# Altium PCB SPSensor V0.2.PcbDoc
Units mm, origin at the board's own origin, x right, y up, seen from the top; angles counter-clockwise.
Board outline 20.98 x 57.97 mm, 4 copper layers (TopLayer, GND, PWR, BottomLayer); 80 components, 54 nets, 260 pads, 87 vias.
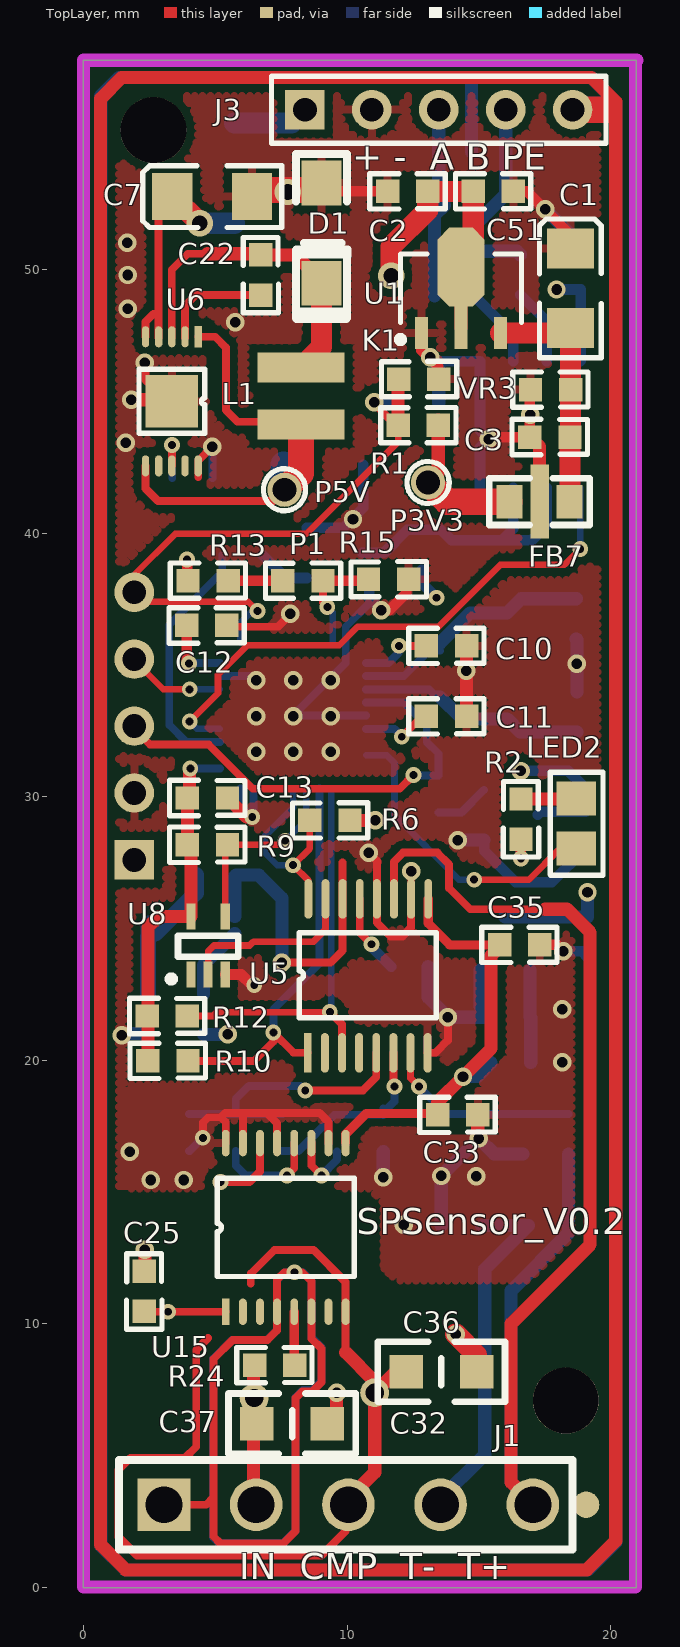
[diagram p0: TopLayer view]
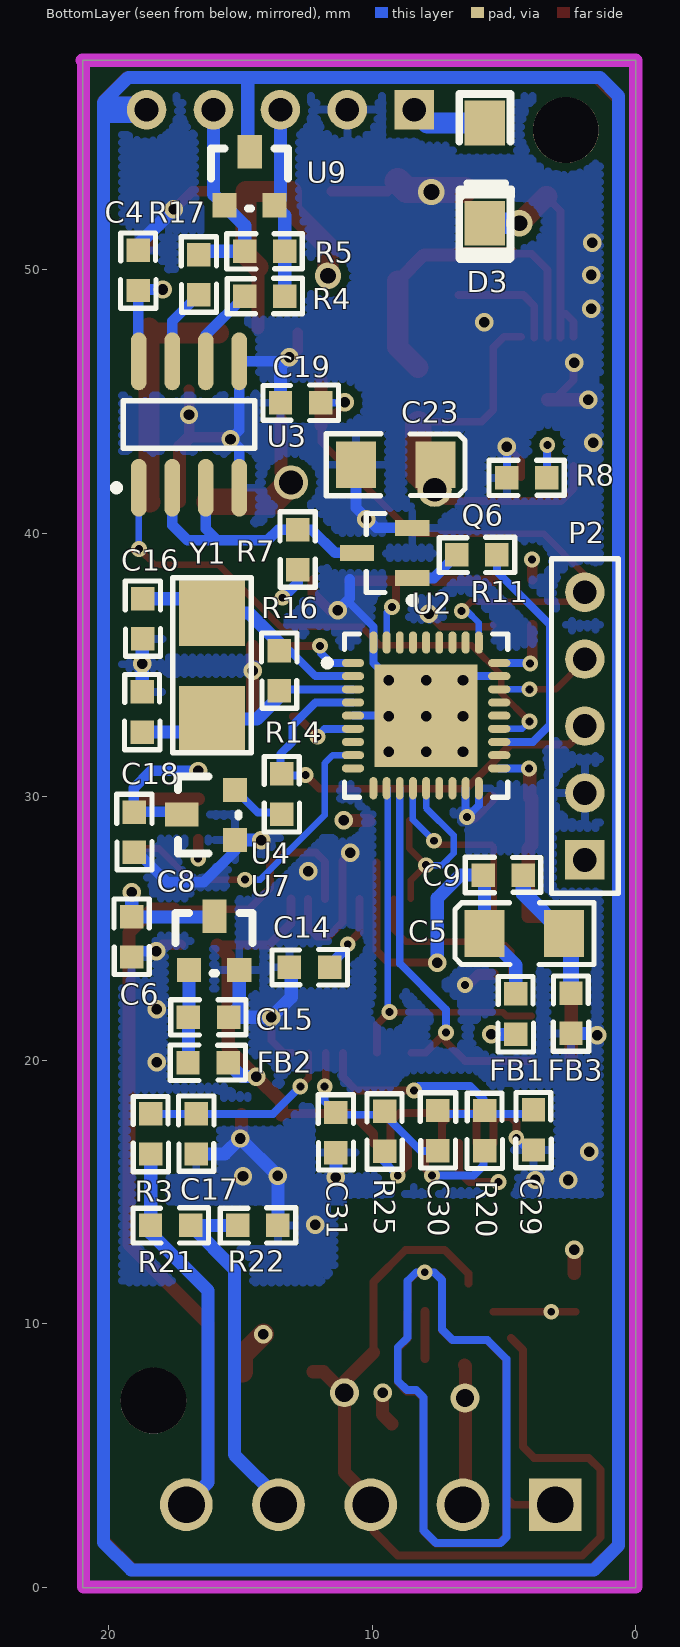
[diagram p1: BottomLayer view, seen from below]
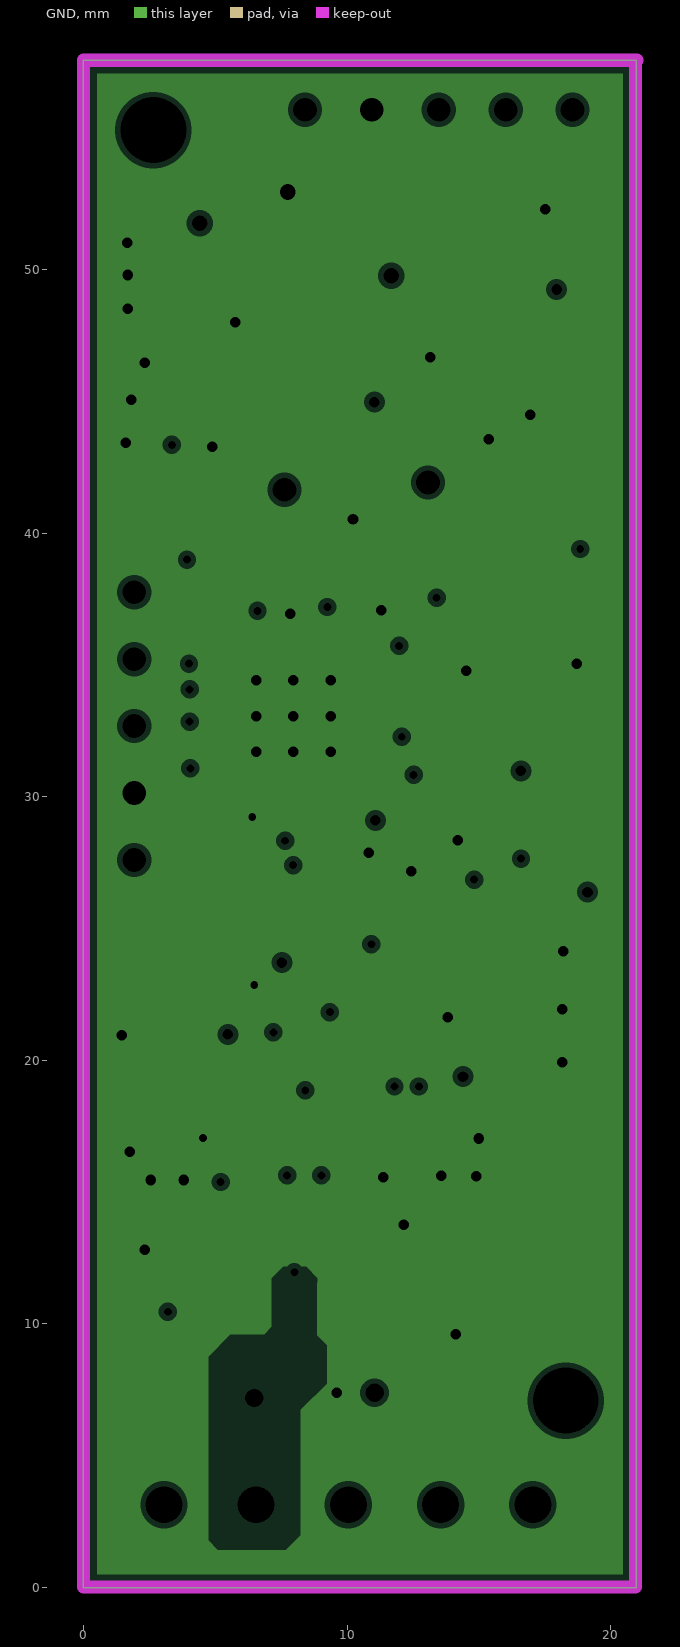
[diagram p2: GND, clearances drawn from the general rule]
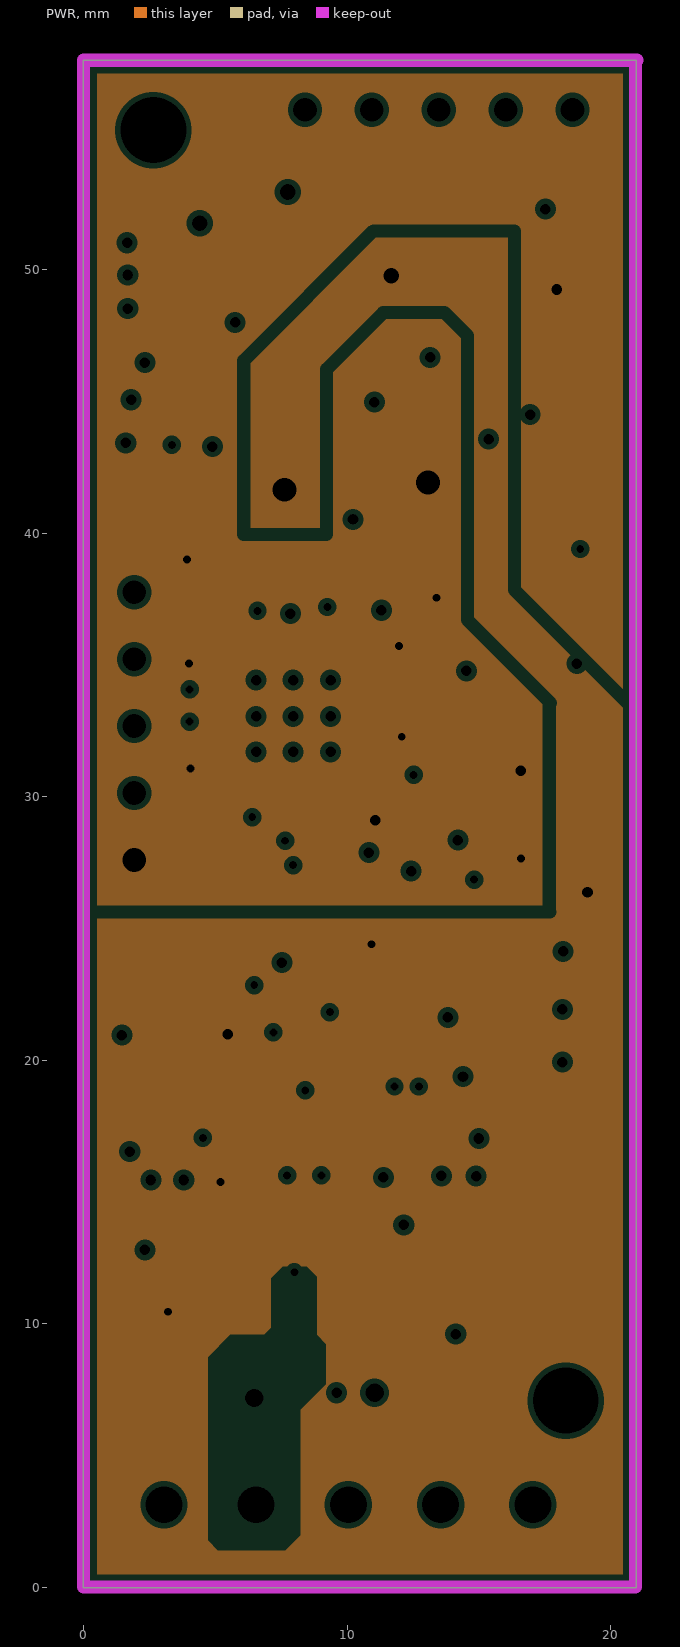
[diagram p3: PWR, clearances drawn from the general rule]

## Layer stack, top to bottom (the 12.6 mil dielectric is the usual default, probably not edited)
TopLayer: signal copper 0.0356
Dielectric: core 0.32, FR-4, Dk 4.8
GND: plane copper 0.0356, net GND
Dielectric: prepreg 0.32, FR-4, Dk 4.8
PWR: plane copper 0.0356, net (Multiple Nets)
Dielectric: core 0.32, FR-4, Dk 4.8
BottomLayer: signal copper 0.0356

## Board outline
-0.006,-0.025 20.975,-0.025 20.975,57.95 -0.006,57.95

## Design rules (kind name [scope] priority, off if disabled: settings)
Clearance Clearance_poly [InPolygon] p1: gap=0.3
Clearance [All] p2: gap=0.15
ComponentClearance [All] p1: gap=0.15 collisioncheckmode=3 verticalgap=0.254 showdistances=FALSE
FabricationTestPointUsage TestPointUsage [All] p1: valid=0 allowmultiple=FALSE
FabricationTestpoint Testpoint [All] p1: side=3 testpointundercomponent=TRUE minsize=1.016 maxsize=2.54 preferedsize=1.524 minholesize=0.508 maxholesize=1.016 preferedholesize=0.813 testpointgrid=0.025 allowsidetop=TRUE allowsidebottom=TRUE usegrid=TRUE gridtolerance=0
HoleSize [All] p1: absolutevalues=TRUE maxlimit=5.08 minlimit=0.025 maxpercent=80.000 minpercent=20.000
MinimumSolderMaskSliver [All] p1: minsoldermaskwidth=0.15
PlaneClearance [All] p1: clearance=0.2
PlaneConnect [All] p1: planeconnectstyle=Relief reliefexpansion=0.3 reliefentries=4 reliefconductorwidth=0.3 reliefairgap=0.3
PolygonConnect PolygonConnect_via [IsVia] p1: connectstyle=Direct reliefconductorwidth=0.254 reliefentries=4 polygonreliefangle="90 Angle"
PolygonConnect [All] p2: connectstyle=Relief reliefconductorwidth=0.3 reliefentries=4 polygonreliefangle="90 Angle"
RoutingVias [All] p1: holewidth=0.305 width=0.61 viastyle="Through Hole" minholewidth=0.254 minwidth=0.508 maxholewidth=2 maxwidth=5
SilkToSilkClearance [All] p1: silktosilkclearance=0
SilkscreenOverComponentPads [All] p1: minsilkscreentomaskgap=0
SolderMaskExpansion [All] p1: expansion=0.102
Width [All] p1: maxlimit=5.08 minlimit=0.1 preferedwidth=0.254
19 further rules are at their usual default settings.

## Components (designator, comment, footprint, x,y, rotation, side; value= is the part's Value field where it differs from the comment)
C1 "10uF" SM1206 18.475,49.3 r90 top
C2 "1uF" SM0603 12.3,53.025 r0 top
C3 "1uF" SM0603 17.7,43.7 r0 top
C4 "0.1uF" SM0603 18.925,49.975 r90 bottom
C5 "10uF" SM1206 4.225,24.8 r0 bottom
C6 "4.7uF" SM0603 19.075,24.675 r270 bottom
C7 "4.7uF/50V" SM1206 4.875,52.775 r180 top
C8 "0.1uF" SM0603 18.975,28.65 r270 bottom
C9 "0.1uF" SM0603 5.025,27.075 r180 bottom
C10 "0.1uF" SM0603 13.775,35.775 r0 top
C11 "0.1uF" SM0603 13.775,33.1 r0 top
C12 "0.1uF" SM0603 4.675,36.55 r0 top
C13 "0.1uF" SM0603 4.7,30 r0 top
C14 "0.1uF" SM0603 12.375,23.475 r0 bottom
C15 "1uF" SM0603 16.21,21.675 r180 bottom
C16 "22pF" SM0603 18.65,36.75 r270 bottom
C17 "1uF" SM0603 16.625,17.2 r270 bottom
C18 "22pF" SM0603 18.775,33.215 r90 bottom
C19 "0.1uF" SM0603 12.715,44.9 r0 bottom
C22 "0.47uF" SM0603 6.675,49.8 r90 top
C23 "22uF" SM1206 9.1,42.6 r180 bottom
C25 "0.1uF" SM0603 2.25,11.225 r90 top
C29 "1uF" SM0603 3.925,17.35 r90 bottom
C30 "100pF" SM0603 7.45,17.325 r270 bottom
C31 "1uF" SM0603 11.325,17.25 r270 bottom
C33 "0.1uF" SM0603 14.2,17.975 r0 top
C35 "0.1uF" SM0603 16.55,24.425 r0 top
C36 "1nF" 0805A 12.241,8.172 r0 top
C37 "1nF" 0805A 6.575,6.2 r0 top
C51 "0.1uF" SM0603 15.55,53.025 r0 top
D1 "CD1607-B140" 1206D 9.025,53.1 r270 top
D3 "M7" 1206D 5.725,55.375 r270 bottom
FB1 "BLM18PG600SN1" SM0603 4.6,21.75 r90 bottom
FB2 "BLM18PG600SN1" SM0603 16.225,19.95 r180 bottom
FB3 "BLM18PG600SN1" SM0603 2.5,21.775 r90 bottom
FB7 "NFM21PC105B1C3" NFM21PC105 18.45,41.2 r180 top
J1 "Header 4" CON1x5-3.5mm 3.05,3.125 r0 top
J3 "Header 5" HDR1X5 8.4,56.075 r0 top
K1 "KEY1" SM0603 12.725,45.8 r180 top (schematic designator R1)
L1 "LPS3010-472ML" LPS3010 8.25,46.29 r270 top
LED2 "RUN" SM0805 18.675,29 r270 top
P1 "NC" sm0603 8.325,38.15 r180 top
P2 "Header 5" HDR1X5 1.925,27.6 r90 bottom
P3V3 "TestPoint" "test point" 13.075,41.925 r90 top
P5V "TestPoint" "test point" 7.625,41.65 r90 top
Q6 "MMBT3904" SOT23_N 9.525,39.25 r0 bottom
R1 "10K" SM0603 12.7,44.05 r180 top
R2 "560R" SM0603 16.55,29.15 r90 top
R3 "10K" SM0603 18.45,17.2 r90 bottom
R4 "10R" SM0603 14.075,48.95 r0 bottom
R5 "120R" SM0603 14.075,50.75 r180 bottom
R6 "100K" SM0603 9.35,29.05 r180 top
R7 "4.7K" SM0603 12.775,39.375 r270 bottom
R8 "49.9K" SM0603 4.125,42.15 r180 bottom
R9 "100K" SM0603 4.7,28.225 r0 top
R10 "100K" SM0603 3.2,20.025 r0 top
R11 "1K" SM0603 6.025,39.125 r0 bottom
R12 "100K" SM0603 3.175,21.725 r0 top
R13 "1K" SM0603 4.725,38.25 r0 top
R14 "1K" SM0603 13.475,30.1 r90 bottom
R15 "100K" SM0603 11.575,38.2 r180 top
R16 "10M" SM0603 13.475,34.775 r270 bottom
R17 "10R" SM0603 16.525,49.81 r270 bottom
R20 "10K" SM0603 5.775,17.325 r90 bottom
R21 "NC" SM0603 17.65,13.675 r0 bottom
R22 "0R" SM0603 14.34,13.675 r0 bottom
R24 "10M" SM0603 7.25,8.475 r0 top
R25 "10K" SM0603 9.575,17.3 r90 bottom
U1 "RT9166A-33PXL" SOT89L 14.325,49.3 r90 top
U2 "STM32F103TBU6" VFQN36_V 7.95,33.075 r180 bottom locked
U3 "MAX3485CSA" NSO8_N 16.95,44.125 r90 bottom
U4 "CAT809VTBI-GT3" SOT-23 17.35,30.686 r90 bottom
U5 "AD7793BRU" AD7793 10.795,23.2 r90 top
U6 "LT3971IMSE-5" LT3971 3.35,45.005 r180 top
U7 "AD1584BRTZ" SOT-23 14.614,25.575 r180 bottom
U8 "SN74LV1T34DCK" SN74LV1T34DCK 4.725,24.35 r180 top
U9 "SM712.TCT" SOT-23 13.275,54.6 r180 bottom
U15 "LMP91200" LMP91200 7.67,13.65 r0 top
VR3 "V3.5MLA0603N" SM0603 17.725,45.5 r0 top (schematic designator VA2)
Y1 "8MHz" CY5.4X4.6 16.075,36.95 r270 bottom

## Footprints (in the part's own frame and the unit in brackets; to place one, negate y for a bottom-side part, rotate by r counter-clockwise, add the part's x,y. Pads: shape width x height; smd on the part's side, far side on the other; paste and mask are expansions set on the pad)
0805A [mm]
  rect 1.27x1.27 smd: 1(0,0) 2(2.678,0)
  silkscreen extent -1.07,-1.14 3.75,1.14
1206D [mm]
  rect 1.7x1.524 smd: 1(-0.19,0.003) 2(3.61,0.003)
  silkscreen extent -1.3,-0.97 4.96,0.99
AD7793 [mm]
  rect 1.5x0.3 smd: 1(-2.921,2.286)
  oval 1.5x0.3 smd: 2(-2.921,1.636) 3(-2.921,0.986) 4(-2.921,0.336) 5(-2.921,-0.314) 6(-2.921,-0.964) 7(-2.921,-1.614) 8(-2.921,-2.264) 9(2.921,-2.286) 10(2.921,-1.636) 11(2.921,-0.986) 12(2.921,-0.336) 13(2.921,0.314) 14(2.921,0.964) 15(2.921,1.614) 16(2.921,2.264)
  silkscreen extent -1.59,-2.59 1.64,2.61
CON1x5-3.5mm [mm]
  rect 2x2 hole 1.4: 1(0,0)
  round 2 hole 1.4: 2(3.5,0) 3(7,0) 4(10.5,0) 5(14,0)
  silkscreen extent -1.7,-1.7 15.5,1.7
CY5.4X4.6 [mm]
  rect 2.5x2.5 smd: 1(-0.025,0) 2(4,0)
  silkscreen extent -1.35,-1.49 5.28,1.49
HDR1X5 [mm] "Connector; Header; 5 Position"
  rect 1.5x1.5 hole 0.9: 1(0,0)
  round 1.5 hole 0.9: 2(2.54,0) 3(5.08,0) 4(7.62,0) 5(10.16,0)
  silkscreen extent -1.27,-1.27 11.43,1.27
LMP91200 [mm]
  rect 0.3x1 smd: 1(-2.275,-3.2)
  oval 0.3x1 smd: 2(-1.625,-3.2) 3(-0.975,-3.2) 4(-0.325,-3.2) 5(0.325,-3.2) 6(0.975,-3.2) 7(1.625,-3.2) 8(2.275,-3.2) 9(2.275,3.2) 10(1.625,3.2) 11(0.975,3.2) 12(0.325,3.2) 13(-0.325,3.2) 14(-0.975,3.2) 15(-1.625,3.2) 16(-2.275,3.2)
  silkscreen extent -2.6,-1.87 2.6,1.87
LPS3010 [mm]
  rect 1.14x3.3 smd: 1(0,0) 2(2.16,0)
LT3971 [mm]
  rect 0.28x0.8 smd: 1(-1,-2.45)
  oval 0.28x0.8 smd: 2(-0.5,-2.45) 3(0,-2.45) 4(0.5,-2.45) 5(1,-2.45) 6(1,2.45) 7(0.5,2.45) 8(0,2.45) 9(-0.5,2.45) 10(-1,2.45)
  rect 2x2 smd: 11(0,0)
  silkscreen extent -1.25,-1.21 1.25,1.22
NFM21PC105 [mm]
  rect 1x1.27 smd: 1(0.01,0.008) 2(2.286,0)
  rect 0.7x2.8 smd: 3(1.143,0)
  silkscreen extent -0.76,-0.89 3.05,0.89
NSO8_N [mm] "SOIC, 8-Leads, Body 4.9x3.9mm, Pitch 1.27mm, IPC Medium Density"
  oval 2.2x0.6 smd: 1(-2.4,1.905) 2(-2.4,0.635) 3(-2.4,-0.635) 4(-2.4,-1.905) 5(2.4,-1.905) 6(2.4,-0.635) 7(2.4,0.635) 8(2.4,1.905)
  silkscreen extent -2.52,-2.5 0.9,2.88, body extent -2,-2.5 2,2.5, height 1.75
SM0603 [mil]
  rect 35x35 smd: 1(-30,-2) 2(30,-2)
  silkscreen extent -57,-28 56,24
sm0603 [mil]
  rect 35x35 smd: 1(-30,-2) 2(30,-2)
  silkscreen extent -57,-28 56,24
SM0805 [mm]
  rect 1.3x1.5 smd: 1(-0.933,0.022) 2(0.967,0.022)
  silkscreen extent -1.93,-0.97 1.98,1.04
SM1206 [mil]
  rect 60x70 smd: 1(59.5,0) 2(-59.5,0)
  silkscreen extent -104,-46 104,46
SN74LV1T34DCK [mm]
  rect 0.35x1 smd: 1(0.65,1.1) 2(0,1.1) 3(-0.65,1.1) 4(-0.65,-1.1) 5(0.65,-1.1)
  silkscreen extent -1.14,-0.38 1.52,1.4
SOT23_N [mm] "SOT23, 3-Leads, Body 2.9x1.3mm, Pitch 0.95mm, Lead Span 2.3mm, IPC Medium Density"
  rect 1.3x0.6 smd: 1(-1.05,0.95) 2(-1.05,-0.95) 3(1.05,0)
  silkscreen extent -1.17,-1.5 0.7,1.92, body extent -0.7,-1.5 0.7,1.5, height 1.1
SOT89L [mm] "SOT89, 3-Leads, Body 4.5x2.4 mm, Pitch 1.5mm, Lead Span 4.1mm, IPC High Density"
  rect 1.2x0.5 smd: 1(-1.7,1.5) 3(-1.7,-1.5)
  rect 1.6x0.5 smd: 2(-1.5,0)
  oct 3x1.8 smd: 2(0.8,0)
  silkscreen extent -2.07,-2.3 1.3,2.42, body extent -1.3,-2.3 1.3,2.3, height 1.6
SOT-23 [mil]
  rect 36x36 smd: 1(-91.86,-84.66) 2(-16.86,-84.66)
  rect 36x50 smd: 3(-53.86,-4.66)
  silkscreen extent -112,-90 3,0
"test point" [mm]
  round 1.3 hole 0.9: 1(0,0)
  silkscreen extent -0.8,-0.8 0.8,0.8
VFQN36_V [mm] "QFN, 36-Leads, Body 6x6mm, Pitch 0.5mm, ST Recommended"
  oval 0.85x0.3 smd: 1(-2.775,2) 2(-2.775,1.5) 3(-2.775,1) 4(-2.775,0.5) 5(-2.775,0) 6(-2.775,-0.5) 7(-2.775,-1) 8(-2.775,-1.5) 9(-2.775,-2) 19(2.775,-2) 20(2.775,-1.5) 21(2.775,-1) 22(2.775,-0.5) 23(2.775,0) 24(2.775,0.5) 25(2.775,1) 26(2.775,1.5) 27(2.775,2)
  oval 0.3x0.85 smd: 10(-2,-2.755) 11(-1.5,-2.755) 12(-1,-2.755) 13(-0.5,-2.755) 14(0,-2.755) 15(0.5,-2.755) 16(1,-2.755) 17(1.5,-2.755) 18(2,-2.755) 28(2,2.775) 29(1.5,2.775) 30(1,2.775) 31(0.5,2.775) 32(0,2.775) 33(-0.5,2.775) 34(-1,2.775) 35(-1.5,2.775) 36(-2,2.775)
  rect 3.9x3.9 smd: 37(0,0)
  silkscreen extent -3.88,-3.1 3.1,3.1, body extent -3.05,-3.05 3.05,3.05, height 1

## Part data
C1 C2 C3 C10 C11 C12 C13 C16 C18 C19: library part Cap, "Capacitor"
C4 C8: library part Cap, "Capacitor, X7R Ceramic"
C5: library part CAPE, "极性"
C6 C7 C9 C14 C15 C22 C25 C29 C30 C31 C33 C35 C36 C37 C51: library part CAP, "Capacitor"
C17: library part CA, "电?"
C23: library part C, "极性"
D1: library part DIODE, "Diode"
D3: library part "Diode 1N4007", "1 Amp General Purpose Rectifier"
FB1 FB3 L1: library part INDUCTOR
FB2 FB7: library part Inductor, "Inductor"
J1: "Header, 4-Pin"
J3 P2: "Header, 5-Pin"
K1: library part "Header 2", "Header, 2-Pin"
LED2: library part LED0, "Typical INFRARED GaAs LED"
P1: library part Head, "Header, 2-Pin, 2.54mm, 排?"
Q6: "NPN Switching Transistor"
R1 R2 R4 R5 R7 R11 R16 R17: library part Res2, "Resistor"
R3 R6 R9 R10 R12 R20 R21 R22 R25: library part RE, "电?"
R8 R13 R14 R15: library part R, "电?"
R24: library part RES, "电?"
U1: library part "Header 3", "Header, 3-Pin"
U2: library part STM32F103T8U6, "STM32 ARM-based 32-bit MCU with 64 Kbytes Flash, 36-pin VFQFPN, Industrial Temperature"
U3: library part MAX485CSA, "Low-Power, Slew-Rate-Limited RS-485/RS-422 Transceiver"
U4: library part CAT809, "Onsemi R"
U5: library part AD7793
U6: library part LT3971
U7: library part "Header 3", "4.096V reference"
U8: library part SN74LV1T34, "1 Channel Level Converter"
U9: library part "Header 3", "Asymmerical TVS Diode for RS485"
VR3: library part "D Zener", "Zener Diode"
Y1: library part XTAL, "Crystal Oscillator"

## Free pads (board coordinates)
  round 1 smd: 0(19.075,3.125)
  round 2.5 hole 2.5: ""(2.65,55.3) ""(18.3,7.075)
  round 1.1 hole 0.7: ""(6.475,7.175) ""(11.05,7.375)

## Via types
v1: diameter 0.7, hole 0.4, TopLayer to BottomLayer, 53 vias
v2: diameter 0.6, hole 0.3, TopLayer to BottomLayer, 31 vias
v3: diameter 1, hole 0.6, TopLayer to BottomLayer, 3 vias

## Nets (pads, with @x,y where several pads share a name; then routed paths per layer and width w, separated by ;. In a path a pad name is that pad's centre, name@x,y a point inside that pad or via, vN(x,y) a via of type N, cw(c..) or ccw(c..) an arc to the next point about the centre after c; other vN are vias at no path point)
+24V: D3.1 J3.1 | length 2.9
  BottomLayer w0.8: D3.1 7.89,55.565 J3.1
BOOT0: P1.1 R15.2 U2.35 | length 4.3
  TopLayer w0.3: P1.1 9.087,37.363 v2(9.25,37.2)
  TopLayer w0.4: P1.1@9.137,38.201 R15.2@10.852,38.201
  BottomLayer w0.25: v2(9.25,37.2) 9.45,37 U2.35
  BottomLayer w0.3: v2(9.25,37.2) v2@9.25,37.3
DVDD: C5.1 C9.1 FB1.2 U5.14 | length 14.8
  TopLayer w0.3: v1(7.525,23.7) 9.375,23.7 9.831,24.156 U5.14 9.831,27.494
  BottomLayer w0.5: FB1.2 4.549,23.613 C5.1 ; C5.1@5.736,25.45 5.736,26.973 C9.1 6.651,27.024 7.525,26.15 v1(7.525,23.7)
EARTH: J3.5 U9.3 | length 306
  TopLayer w0.3: J3.5@18.56,56.175 J3.5@18.685,56.3
  TopLayer w0.5: 0.644,1.606 0.644,56.494 1.45,57.3 19.275,57.3 20.2,56.375 20.2,1.75 19.1,0.65 1.6,0.65 0.644,1.606
  TopLayer w1: J3.5 19.875,56.075
  BottomLayer w0.5: U9.3@14.718,54.482 14.718,57.243 ; 20.2,55.7 20.2,1.7 19.15,0.65 1.575,0.65 0.65,1.575 0.65,56.6 1.35,57.3 19.25,57.3 20.2,56.35 20.2,55.8
  BottomLayer w1: J3.5 19.925,56.075
GND: C1.1 C2.1 C3.1 C4.2 C6.2 C7.2 C8.2 C10.2 C11.2 C12.2 C13.2 C14.2 C15.2 C16.2 C17.2 C18.2 C19.2 C23.2 C25.2 C29.1 C31.2 C33.2 C35.2 C36.2 C37.2 C51.2 D1.1 FB3.1 FB7.3 J3.2 K1.1 P2.2 Q6.2 R8.1 R15.1 R22.1 U1.1 U2.5 U2.17 U2.18 U2.26 U2.36 U2.37 U3.4 U3.5 U4.1 U5.8 U5.10 U5.12 U6.10 U6.11 U7.2 U8.3 U15.10 U15.13 U15.15 U15.16 VR3.1 | length 107.4
  TopLayer w0.3: v1@2.35,46.475 2.35,45.816 U6.11@3.1,45.065 ; 4.35,42.13 U6.10 4.35,42.75 v1(4.887,43.287) ; v2(4.525,17.051) 4.525,17.625 4.733,17.833 5.208,17.833 ; U15.16 5.395,17.647 5.208,17.833 ; C12.2 5.486,36.45 7.375,36.45 7.85,36.925 v1(7.85,36.95) ; U15.15 6.045,17.925 5.969,18 ; U15.13 7.345,17.6 6.944,18 ; U15.10 9.295,17.655 8.95,18 6.944,18 ; v1(10.825,27.875) 11.131,27.569 U5.12 11.131,25.219 11.65,24.7 12.1,24.7 12.431,25.031 U5.10 ; U5.8 13.354,20.279 13.825,20.75 v1(13.825,21.625) ; 5.208,17.833 5.375,18 5.969,18 ; 5.969,18 6.944,18
  TopLayer w0.4: U8.3 5.975,23.25 6.375,22.85 v2(6.475,22.85) ; D1.1@9.028,53.365 9.419,52.974 C2.1 ; v1(11.3,37.075) 11.6,37.075 12.25,37.725 R15.1@12.25,38.2 ; U1.1 12.825,46.95 13.462,46.313 K1.1@13.462,45.824 ; v1(15.375,43.575) 15.449,43.649 C3.1 16.938,45.424 VR3.1 ; C51.2 16.826,52.974 18.475,51.325 C1.1 ; C35.2@17.272,24.375 17.95,24.375 v1(18.2,24.125)
  TopLayer w0.5: v1@1.762,45.065 v1(1.8,45.065) 3.1,45.065 U6.11@3.344,45.065 ; C25.2@2.325,11.897 v1(2.325,12.8) ; C13.2 6.186,29.225 v2(6.4,29.225) ; C37.2 9.6,6.547 v1(9.6,7.375) ; C11.2 C10.2 ; v1@14.925,17.025 v1@14.962,17.025 ; C33.2 v1@14.962,17.025 ; v1(15,17.025) v1@14.962,17.025 ; C3.1 17.307,43.28 FB7.3
  TopLayer w0.8: v1(14.125,9.6) 14.92,8.805 C36.2
  TopLayer w1: C7.2@6.49,53.025 v3@7.75,53.025 ; v3(7.75,52.95) v3@7.75,53.025 ; D1.1@9.028,53.365 8.687,53.025 v3@7.75,53.025
  BottomLayer w0.3: C29.1@4,16.553 4.027,16.553 v2(4.525,17.051) ; R8.1 v1(4.887,43.287) ; U2.26 U2.37@6.45,34.575 ; U2.18 5.95,29.675 v2(6.4,29.225) 6.45,29.275 U2.17 ; U2.5 U2.37 9.95,35.075 U2.36 9.95,36.45 10.85,37.35 10.85,37.525
  BottomLayer w0.4: Q6.2 9.85,40.2 10.611,40.961 C23.2 ; 10.85,38.25 10.85,37.525 v1(11.3,37.075) ; v1@13.3,46.525 U3.5 15.045,43.905 v1(15.375,43.575) 15.045,43.245 U3.4 ; U4.1 15.2,27.95 16.4,26.75 17.775,26.75 C8.2@19.05,28.025 ; v1(18.2,24.125) 18.914,24.125 C6.2
  BottomLayer w0.5: v1(1.45,20.951) 1.512,21.013 FB3.1 ; v1@11.375,15.725 C31.2@11.375,16.525 ; C14.2@13.072,23.55 13.072,22.378 v1(13.825,21.625) C15.2 ; v1(13.15,46.675) 13.3,46.525 13.477,46.348 C19.2 ; R22.1 v1(13.578,15.603) v1(15,17.025) 15.587,16.438 C17.2 ; v1(14.203,28.353) U4.1 ; U7.2 15.042,22.03 C15.2 ; C15.2 C15.2 ; v1(17.525,52.3) 18.874,50.951 C4.2 ; C16.2 18.724,35.965 v1(18.724,35.05) C18.2
  other v1: 12.15,13.75 2.55,15.45 3.8,15.45 11.375,15.55 14.9,15.6 1.75,16.525 18.175,19.925 18.175,21.925 12.431,27.171 6.55,31.7 7.95,31.7 9.375,31.7 6.55,33.05 7.95,33.05 9.375,33.05 6.55,34.425 7.95,34.425 9.375,34.425 14.525,34.775 10.225,40.525 1.6,43.425 16.95,44.5 2.325,46.475 5.75,48 1.675,48.525 1.675,49.8 1.65,51.025
GUARD: J1.1 U15.4 U15.6 | length 55.5
  TopLayer w0.3: J1.1 4.65,3.125 4.925,3.4 ; U15.6 8.645,11.605 8.3,11.95 v2(8,11.95) 7.625,11.95 7.345,11.67 U15.4 7.345,9.745 6.975,9.375 5.65,9.375 4.925,8.65 4.925,3.4 ; U15.6@8.65,10.45 8.65,9.425 9.025,9.05 9.025,7.775 8.675,7.425 8.3,7.425 8.05,7.175 8.05,2.125 7.575,1.65 5.2,1.65 4.925,1.925 4.925,3.4
  BottomLayer w0.3: 4.9,1.9 5.125,1.675 7.575,1.675 8.05,2.15 8.05,7.2 8.325,7.475 8.675,7.475 9.025,7.825 9.025,9.1 8.65,9.475 8.65,11.625 8.325,11.95 v2(8,11.95) 7.65,11.95 7.35,11.65 7.35,9.775 6.95,9.375 5.625,9.375 4.9,8.65 4.9,1.9
JTCK: C19.1 K1.2 P2.5 R1.2 U2.28 | length 23.9
  TopLayer w0.25: v2(6.6,37.05) 6.25,37.4 2.285,37.4 P2.5 1.925,38.425 3.475,39.975 8.45,39.975 11.938,43.463 R1.2
  TopLayer w0.3: v1(11.038,44.975) 11.025,44.975 11.001,44.951 11.651,44.301 R1.2@11.938,44.301
  TopLayer w0.5: R1.2 11.938,44.301 K1.2@11.938,45.824
  BottomLayer w0.25: U2.28 5.95,36.6 6.4,37.05 v2(6.6,37.05)
  BottomLayer w0.3: v1(11.038,44.975) 11.025,44.975 11.001,44.951 C19.1
JTDI: U2.29
JTDO: U2.30
JTMS: P2.4 U2.25 | length 3.8
  TopLayer w0.25: P2.4@1.875,35.225 3.025,34.075 v2(4.025,34.075)
  BottomLayer w0.25: v2(4.025,34.075) U2.25
JTRST: U2.31
LED_S1: U2.23
LED_S2: LED2.2 U2.8 | length 11.6
  TopLayer w0.25: v2(14.825,26.85) 16.9,26.85 18.083,28.033 LED2.2
  BottomLayer w0.25: U2.8 11.5,31.575 11.8,31.275 11.8,29.3 14.25,26.85 v2(14.825,26.85)
MCU_RXD1: U2.22 U3.1 | length 21.5
  TopLayer w0.25: v2(4.025,32.85) 5.1,33.925 5.1,34.625 6.225,35.75 9.7,35.75 10.4,36.45 13.475,36.45 15.825,38.8 18.25,38.8 v2(18.85,39.4)
  BottomLayer w0.25: v2(4.025,32.85) 4.3,32.575 U2.22 ; v2(18.85,39.4) 18.855,39.405 U3.1
MCU_TXD1: R11.1 U2.21 | length 9.5
  BottomLayer w0.3: U2.21 3.9,32.075 3.25,32.725 3.25,36.525 5.263,38.538 R11.1
MISO1: R9.2 U2.13 U8.4 | length 7.3
  TopLayer w0.25: U8.4 5.375,28.087 R9.2 7.499,28.174 v2(7.65,28.325)
  BottomLayer w0.25: v2(7.65,28.325) 8.45,29.125 U2.13
MOSI1: R6.2 U2.14 U5.16 | length 7.6
  TopLayer w0.25: U5.16 8.531,26.819 v2(7.95,27.4) 8.588,28.038 R6.2
  BottomLayer w0.25: v2(7.95,27.4) 7.35,27.4 6.9,27.85 6.9,28.525 7.95,29.575 U2.14
NetC1_2: C1.2 C3.2 FB7.1 U1.3 VR3.2 | length 9.3
  TopLayer w0.8: U1.3 18.286,47.6 C1.2 18.475,43.662 C3.2 18.462,41.214 FB7.1
NetC5_2: C5.2 C9.2 FB3.2 | length 5.5
  BottomLayer w0.6: FB3.2 2.449,24.699 C5.2@2.45,25.186 ; C5.2 4.263,26.349 C9.2
NetC7_1: C7.1 D3.2 U6.4 U6.5 | length 9.5
  TopLayer w0.3: U6.5 2.35,48.025 2.65,48.325 2.844,48.325 ; U6.4@2.844,47.423 2.844,48.325 ; C7.1 3.364,52.739 2.844,52.219 2.844,48.325
  TopLayer w0.8: C7.1 3.4,52.775 v3(4.41,51.765)
  BottomLayer w0.8: v3(4.41,51.765) D3.2
NetC15_1: C15.1 FB2.1 U7.1 | length 3.5
  BottomLayer w0.5: U7.1 16.947,21.649 C15.1 FB2.1@16.972,19.914
NetC16_1: C16.1 R16.1 U2.2 Y1.1 | length 9.1
  BottomLayer w0.3: U2.2 12.15,34.575 13.112,35.537 R16.1
  BottomLayer w0.5: R16.1@13.526,35.826 14.675,36.975 Y1.1 16.612,37.512 C16.1
NetC17_1: C17.1 R3.2 U5.7 | length 7.5
  TopLayer w0.25: U5.7 12.409,19.316 v2(12.725,19)
  BottomLayer w0.3: v2(12.725,19) 13.763,17.962 C17.1 R3.2
NetC18_1: C18.1 R16.2 U2.3 Y1.2 | length 8.7
  BottomLayer w0.3: U2.3 13.11,34.075 13.298,33.887 R16.2@13.526,33.887
  BottomLayer w0.5: R16.2@13.526,33.787 14.363,32.95 Y1.2 ; Y1.2@16.038,32.913 Y1.2 ; C18.1 16.572,32.453 Y1.2
NetC22_1: C22.1 U6.2 | length 4.3
  TopLayer w0.3: U6.2@3.844,47.423 3.844,48.624 4.257,49.038 C22.1
NetC22_2: C22.2 D1.2 L1.1 U6.3 | length 12.6
  TopLayer w0.3: U6.3@3.344,47.423 3.344,49.999 3.952,50.607 4.7,50.607
  TopLayer w0.5: 4.7,50.607 C22.2@6.8,50.607 ; C22.2 8.031,50.562 D1.2@9.028,49.565
  TopLayer w0.8: L1.1 9.028,47.068 D1.2@9.028,49.565
NetC29_2: C29.2 C30.1 R20.2 U5.5 | length 10.9
  TopLayer w0.3: v2(8.412,18.85) 10.6,18.85 11.109,19.359 U5.5
  BottomLayer w0.3: C29.2@4,17.95 R20.2@5.775,17.95 ; C30.1@7.55,17.95 R20.2@5.775,17.95 ; v2(8.412,18.85) 8.237,19.025 6.275,19.025 5.775,18.525 R20.2@5.775,17.95
NetC30_2: C30.2 C31.1 R25.2 U5.6 | length 7
  TopLayer w0.3: v2@11.759,19.034 U5.6
  BottomLayer w0.3: C30.2@7.55,16.553 8.153,16.553 9.525,17.925 11.372,17.925 11.375,17.922 C31.1@11.375,18.167 ; C31.1 11.8,18.436 v2(11.8,19)
NetLED2_1: LED2.1 R2.2 | length 2.1
  TopLayer w0.5: R2.2 18.676,29.912 LED2.1
NetP1_2: P1.2 R13.2 | length 2.3
  TopLayer w0.4: R13.2@5.322,38.25 5.371,38.201 P1.2@7.613,38.201
NetQ6_1: Q6.1 R11.2 | length 2.1
  BottomLayer w0.4: R11.2 7.663,38.3 Q6.1
NetQ6_3: Q6.3 R7.1 U3.2 U3.3 | length 11.4
  BottomLayer w0.4: Q6.3 11.4,39.25 12.287,40.137 R7.1 13.563,40.137 13.975,39.725 15.875,39.725 ; U3.3 16.315,40.165 15.875,39.725 ; U3.2 17.585,40.31 17,39.725 15.875,39.725
NetR4_2: R4.2 U3.6 | length 3.1
  BottomLayer w0.4: R4.2 16.315,47.523 U3.6
NetR8_2: R8.2 U6.8 | length 2.1
  TopLayer w0.3: U6.8 v2(3.35,43.35)
  BottomLayer w0.3: v2(3.35,43.35) 3.363,43.337 R8.2
NetR14_1: R14.1 U4.2 | length 2.1
  BottomLayer w0.3: R14.1@13.475,29.4 14.341,29.4 U4.2
NetR17_2: R17.2 U3.7 | length 2.9
  BottomLayer w0.4: R17.2 17.585,48.039 U3.7
NetR20_1: R20.1 U15.12 | length 4
  TopLayer w0.3: v2(7.725,15.625) 7.995,15.895 U15.12
  BottomLayer w0.3: R20.1@5.775,16.553 5.775,16 6.15,15.625 v2(7.725,15.625)
NetR24_2: R24.2 U15.5 | length 1.8
  TopLayer w0.35: R24.2@7.995,8.687 U15.5
NetR25_1: R25.1 U15.11 | length 2.5
  TopLayer w0.3: U15.11 8.645,16.005 v2(9.025,15.625)
  BottomLayer w0.3: v2(9.025,15.625) 9.625,16.225 R25.1@9.625,16.528
NetU5_15: U5.15 U8.2 | length 6.8
  TopLayer w0.25: U8.2 4.725,24.125 4.95,24.35 6.3,24.35 6.45,24.5 8.725,24.5 9.181,24.956 U5.15
PH-CMP: C36.1 J1.3 pad.@11.05,7.375 U15.8 | length 36.2
  TopLayer w0.3: 4.725,9.45 4.275,9 4.275,5.325 3.85,4.9 1.775,4.9 1.325,4.45 1.325,1.9 2.025,1.2 9.025,1.2 9.95,2.125 J1.3@9.95,3.25 ; 6.344,11.525 6.344,11.895 7.25,12.8 8.725,12.8 9.945,11.58 U15.8 9.945,8.905
  TopLayer w0.5: 9.945,8.905 11.05,7.8 pad.@11.05,7.375 ; J1.3@9.95,3.25 11.05,4.35 pad.@11.05,7.375 ; C36.1 11.847,8.172 pad.@11.05,7.375
PH-INP: C37.1 J1.2 pad.@6.475,7.175 R24.1 | length 5.3
  TopLayer w0.5: J1.2@6.45,3.1 6.45,7.175 6.45,8.386 R24.1
RS485+: J3.3 R4.1 R5.2 U9.2 | length 7.3
  BottomLayer w0.5: R4.1 R5.2 13.313,52.059 U9.2 13.48,52.673 J3.3
RS485-: J3.4 R5.1 R17.1 U9.1 | length 7.7
  BottomLayer w0.5: J3.4 16.02,52.861 U9.1 14.837,51.678 R5.1 16.449,50.699 R17.1
RST#: P2.3 R14.2 U2.4 | length 17.5
  TopLayer w0.3: P2.3@1.875,32.625 2.525,31.975 4.749,31.975 6.424,30.3 12,30.3 v2(12.525,30.825)
  BottomLayer w0.3: U2.4 12.15,33.575 13.025,32.7 13.025,32.075 13.475,31.625 13.475,30.797 12.553,30.797 v2(12.525,30.825)
RX485: U2.10
SCK1: R10.2 U2.12 U5.1 | length 15.5
  TopLayer w0.3: R10.2 6.474,19.974 7.2,20.7 v2(7.2,21.05) 7.971,20.279 U5.1
  BottomLayer w0.3: v2(7.2,21.05) 7.2,21.925 8.95,23.675 U2.12
SSEL1: R12.2 U2.11 U5.3 | length 15.7
  TopLayer w0.25: R12.2 4.899,21.674 5.05,21.825 v2(9.345,21.825)
  TopLayer w0.3: v2(9.345,21.825) 9.809,21.361 U5.3
  BottomLayer w0.25: v2(9.345,21.825) v2@9.45,21.93 ; v2@9.4,21.93 U2.11@9.4,30.32
TP-IN+: J1.5 R3.1 R21.2 U5.11 | length 48.3
  TopLayer w0.3: U5.11 11.781,27.531 12.125,27.875 13.425,27.875 13.875,27.425 13.875,26.525 14.675,25.725 17.525,25.725
  TopLayer w0.5: J1.5@16.95,3.25 16.225,3.975 16.225,10 19.225,13 19.225,24.85 18.35,25.725 17.525,25.725
  BottomLayer w0.5: J1.5@16.95,3.25 16.225,3.975 16.225,11.25 18.399,13.424 R3.1
TP-IN-: J1.4 R21.1 R22.2 | length 13.7
  BottomLayer w0.5: J1.4@13.45,3.25 15.225,5.025 15.225,12.063 R21.1 R22.2
TX485: U2.9
VCC3.3: C4.1 C8.1 C10.1 C11.1 C12.1 C13.1 FB7.2 P2.1 P3V3.1 R1.1 R2.1 R6.1 R7.2 R9.1 R10.1 R12.1 R13.1 U2.1 U2.6 U2.19 U2.27 U3.8 U4.3 U8.5 | length 40.4
  TopLayer w0.3: v2(11.975,35.725) 11.976,35.724 C10.1 ; v2(12.075,32.275) 12.849,33.049 C11.1
  TopLayer w0.4: C12.1@3.925,36.511 C12.1 3.913,35.137 v2(4,35.05) ; R13.1@3.925,38.25 v2(3.925,39) ; R9.1@3.938,28.249 R9.1@3.963,28.224 ; v2@4.013,31.038 v2(4.05,31.075) ; v2(16.601,27.651) R2.1
  TopLayer w0.5: R10.1 2.438,25.038 2.85,25.45 U8.5 4.075,28.037 R9.1@3.963,28.149 ; R9.1 R9.1@3.963,28.149 ; R9.1@3.938,28.249 C13.1 ; R9.1@3.963,28.224 R9.1@3.963,28.149 ; C13.1@4.013,29.949 v2@4.013,31.038 ; R6.1 v1(11.074,29.101) ; P3V3.1 13.462,42.312 R1.1@13.462,44.301
  TopLayer w1: P3V3.1 13.8,41.2 FB7.2
  BottomLayer w0.3: v2(4,35.05) 3.975,35.075 U2.27 ; v2(4.05,31.075) U2.19 ; U2.6 11.8,32.575 12.075,32.3 v2(12.075,32.275) ; U2.1 11.575,35.075 v2@11.95,35.45
  BottomLayer w0.4: R7.2 12.826,38.124 v2(13.4,37.55) ; v1(16.6,30.975) 18.4,30.975 19.05,30.325 19.05,29.422 17.335,29.422 U4.3 ; v1(17.95,49.25) 18.875,49.25 18.875,46.545 U3.8
VCC5: C2.2 C6.1 C14.1 C23.1 C25.1 C51.1 FB1.1 L1.2 P5V.1 U1.2 U5.13 U6.1 U6.6 U7.3 U15.1 U15.14 | length 41.6
  TopLayer w0.3: C25.1@2.27,10.45 v2(3.2,10.45) U15.1 ; U6.6 2.35,41.7 2.825,41.225 7.2,41.225 P5V.1 ; U6.1 4.994,47.455 5.4,47.05 5.4,44.675 5.844,44.23 L1.2@8.25,44.23 ; v2(5.2,15.375) 6.3,15.375 6.695,15.77 U15.14 ; U5.13 10.481,24.844 v2(10.925,24.4)
  TopLayer w0.5: U1.2@14.325,47.8 U1.2@14.325,50.1
  TopLayer w0.8: v3(11.675,49.775) 11.675,50.875 13.062,52.262 C2.2 C51.1 14.788,50.563 U1.2@14.325,50.1
  TopLayer w1: P5V.1 8.25,42.275 L1.2
  BottomLayer w0.4: v2(10.925,24.4) 10.925,24.3 C14.1@11.675,23.55
  BottomLayer w0.5: FB1.1@4.549,20.975 v1(5.475,20.975) ; U7.3 16.001,25.437 C6.1 v1(19.126,26.374)
  BottomLayer w1: C23.1 7.589,41.686 P5V.1
VREF: C33.1 C35.1 FB2.2 U5.9 U15.9 | length 17
  TopLayer w0.35: U15.9 9.945,17.195 10.725,17.975 13.387,17.975 C33.1 ; U5.9 13.081,25.194 13.9,24.375 C35.1@15.875,24.375
  TopLayer w0.5: C33.1 13.438,18.413 v1(14.4,19.375) 15.463,20.438 15.463,23.963 C35.1@15.875,24.375
  BottomLayer w0.5: v1(14.4,19.375) 14.939,19.375 FB2.2
pads on no net: U2.7 U2.15 U2.16 U2.20 U2.24 U2.32 U2.33 U2.34 U5.2 U5.4 U6.7 U6.9 U8.1 U15.2 U15.3 U15.7

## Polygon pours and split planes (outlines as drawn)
no net on TopSolder "BottomLayer-No Net" (solid): 7.9,12.175 7.5,12.175 7.125,11.8 7.125,9.85 6.95,9.675 6.875,9.6 5.7,9.6 4.7,8.6 4.7,7.95 4.7,1.575 4.9,1.375 7.35,1.375 7.65,1.375 8.225,1.95 8.225,6.625 8.225,7.075 8.375,7.225 8.5,7.35 8.825,7.35 9.2,7.725 9.2,9.2 8.875,9.525 8.875,11.75 8.475,12.15
no net on BottomSolder "BottomLayer-No Net" (solid): 7.975,12.175 7.525,12.175 7.225,11.875 7.125,11.775 7.125,9.95 7.125,9.825 6.9,9.6 6.85,9.55 5.7,9.55 5.6,9.55 4.725,8.675 4.725,1.675 4.95,1.45 7.35,1.45 7.375,1.425 7.6,1.425 8.175,2 8.2,2.025 8.2,6.575 8.2,7.075 8.4,7.275 8.45,7.325 8.75,7.325 8.85,7.325 9.2,7.675 9.2,9.15 8.85,9.5 8.825,9.525 8.825,11.625 8.825,11.75 8.375,12.2
GND on TopLayer "BottomLayer-No Net" (hatched 90Degree grid 0.3 track 0.3, remove dead copper, pour order 6): -0.006,57.95 20.95,57.95 20.95,11.675 21,11.625 11.875,11.625 11.375,12.125 11.375,14.6 10.85,15.125 0.025,15.125 -0.025,15.175
GND on BottomLayer "BottomLayer-No Net" (hatched 90Degree grid 0.3 track 0.3, remove dead copper, pour order 8): -0.006,57.95 21,57.95 21,11.55 12,11.55 11.425,12.125 11.425,14.3 11.375,14.35 10.85,14.875 10.825,14.875 0.075,14.875 0,14.8
GND on GND (split plane): 20.465,0.485 0.505,0.485 0.505,57.44 20.465,57.44
VCC3.3 on PWR (split plane): 20.465,34.092 16.602,37.954 16.602,51.475 16.594,51.54 16.568,51.601 16.528,51.653 16.476,51.693 16.415,51.719 16.35,51.727 11,51.727 10.935,51.719 10.874,51.693 10.822,51.653 5.897,46.728 5.857,46.676 5.831,46.615 5.823,46.55 5.823,39.95 5.831,39.885 5.857,39.824 5.897,39.772 5.949,39.732 6.01,39.706 6.075,39.698 9.225,39.698 9.29,39.706 9.351,39.732 9.403,39.772 9.443,39.824 9.469,39.885 9.477,39.95 9.477,46.121 11.479,48.123 13.596,48.123 14.323,47.396 14.323,36.7 14.331,36.635 14.357,36.574 14.397,36.522 17.423,33.496 17.423,25.877 0.505,25.877 0.505,57.44 20.465,57.44
VCC5 on PWR (split plane): 16.098,37.85 16.106,37.785 16.132,37.724 16.172,37.672 20.465,33.379 20.465,0.485 0.505,0.485 0.505,25.373 17.7,25.373 17.765,25.381 17.826,25.407 17.878,25.447 17.918,25.499 17.944,25.56 17.952,25.625 17.944,25.69 17.927,25.73 17.927,33.403 17.943,33.424 17.969,33.485 17.977,33.55 17.969,33.615 17.943,33.676 17.903,33.728 14.827,36.804 14.827,47.5 14.819,47.565 14.801,47.608 14.793,47.626 14.776,47.649 14.753,47.678 13.878,48.553 13.826,48.593 13.765,48.619 13.7,48.627 11.375,48.627 11.31,48.619 11.249,48.593 11.197,48.553 9.047,46.403 9.007,46.351 8.981,46.29 8.973,46.225 8.973,40.202 6.327,40.202 6.327,46.446 11.104,51.223 16.098,51.223

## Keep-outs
KeepOutLayer:
  lines w0.5: -0.006,57.95 -0.006,0 10.994,0 20.95,0 20.95,57.95 ; 0.044,57.95 21,57.95

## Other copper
TopLayer:
  pour cut-out: 6.3,47.2 10.275,47.2 10.275,43.15 6.325,43.15 6.3,43.175
GND (plane layer: these items are gaps in the copper):
  pour cut-out: 7.575,12.15 7.15,11.725 7.15,9.875 6.85,9.575 5.575,9.575 4.75,8.75 4.75,1.775 5.1,1.425 7.675,1.425 8.225,1.975 8.225,6.725 9.225,7.725 9.225,9.175 8.85,9.55 8.85,11.55 8.875,11.575 8.875,11.725 8.45,12.15
PWR (plane layer: these items are gaps in the copper):
  pour cut-out: 7.55,12.15 7.125,11.725 7.125,9.85 6.85,9.575 5.575,9.575 4.725,8.725 4.725,1.775 5.1,1.4 7.65,1.4 8.225,1.975 8.225,6.725 9.2,7.7 9.2,9.225 8.85,9.575 8.85,11.775 8.475,12.15
  lines w0.5: -0.05,25.625 17.7,25.625 ; 17.675,25.625 17.675,33.55 ; 17.725,33.55 14.575,36.7 14.575,47.5 13.7,48.375 11.375,48.375 9.225,46.225 9.225,39.95 6.075,39.95 6.075,46.55 11,51.475 16.35,51.475 16.35,37.85 20.95,33.25 20.95,14.275

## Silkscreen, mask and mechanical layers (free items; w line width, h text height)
TopOverlay:
  text "+ -  A B PE" at 10.2,53.8 h1
  text "SPSensor_V0.2" at 10.375,13.4 h1
  text "C32" at 11.625,5.825 h0.8
  text "IN  CMP  T-  T+" at 5.9,0.3 h1
Mechanical1:
  lines w0.3: -1.675,57.95 21.85,57.95 ; -1.206,3.075 26.45,3.075 ; -0.431,0.025 31.15,0.025 ; 0.006,4.125 0.006,78.075 ; 0.3,55.3 4.45,55.3 ; 2.65,-2 2.65,59 ; 15.55,7.05 21.425,7.05 ; 18.325,-2.8 18.325,10.8 ; 20.956,-1.3 20.956,62.025

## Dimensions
-0.975,57.95 to 0.3,55.3 on Mechanical1
2.65,59 to 0,57.725 on Mechanical1
-0.75,3.075 to -0.85,0.025 on Mechanical1
-0.006,4.75 to 20.95,-0.65 on Mechanical1
21.125,57.95 to 20.794,-0.016 on Mechanical1
18.325,-2.8 to 20.975,-1.525 on Mechanical1
21.1,0.025 to 21.425,7.05 on Mechanical1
